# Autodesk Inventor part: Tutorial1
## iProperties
Shininess: 77.0
Length Units: 11269
Angle Units: 11279
Time Units: 11290
Mass Units: 11283
Length Display Precision: 3
Angle Display Precision: 2
Created: 2001-12
Part Number: Tutorial1
Document SubType Name: Modeling
Designer: Renu Muthoo
Density: 1 g/cm^3
Density: 0.0
Volumn: 0.0
Area: 0.0
PropertySet Name: Model Information
Control State: 0
Master: False
Checked Out: False
Author: Renu Muthoo
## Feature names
1. Extrusion1
2. Extrusion2
3. Extrusion3
4. Fillet1
5. Hole2
6. Hole3
